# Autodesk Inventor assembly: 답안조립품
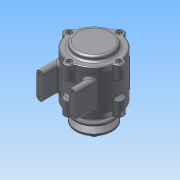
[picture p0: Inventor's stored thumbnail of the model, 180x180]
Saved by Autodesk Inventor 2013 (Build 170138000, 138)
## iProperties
Created: 2015-03
Part Number: 답안조립품
Document SubType Name: Assembly
Designer: ST5
Author: ST5
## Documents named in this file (11)
- C:\Users\ST5\Desktop\450305V1010\답안조립품.iam
- C:\Users\ST5\Desktop\450305V1010\1-본체.ipt
- C:\Users\ST5\Desktop\450305V1010\커버2.ipt
- C:\Users\ST5\Desktop\450305V1010\커버.ipt
- C:\Users\ST5\Desktop\450305V1010\베어링 6204.ipt
- C:\Users\ST5\Desktop\450305V1010\축.ipt
- C:\Users\ST5\Desktop\450305V1010\키(4 x 4 x 12).ipt
- C:\Users\ST5\Desktop\450305V1010\V벨트풀리.ipt
- C:\Users\ST5\Desktop\450305V1010\오일실.ipt
- C:\Users\ST5\Desktop\450305V1010\너트 M12x1.25.ipt
- C:\Users\ST5\Desktop\450305V1010\M 4 x 12.ipt
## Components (15 placed, 7 different names)
1. 1-본체:1
2. KS B 2023 6204 - 20 x 47 x 14:1
3. KS B 2023 6204 - 20 x 47 x 14:2
4. KS B 1311 (I) 4 x 4 x 12:1 — 각도:1
5. 그루브 풀리1:1
6. KS B 2804 D D - 20 32 8:1
7. KS B 1012 클래스 1 일반 - 미터 M12x1.25:1
8. KS B 1003 - 미터 M 4 x 12:1
9. KS B 1003 - 미터 M 4 x 12:2
10. KS B 1003 - 미터 M 4 x 12:3
11. KS B 1003 - 미터 M 4 x 12:4
12. KS B 1003 - 미터 M 4 x 12:5
13. KS B 1003 - 미터 M 4 x 12:6
14. KS B 1003 - 미터 M 4 x 12:7
15. KS B 1003 - 미터 M 4 x 12:8
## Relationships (1: Angle 1)
- 각도:1 [Angle]: KS B 1311 (I) 4 x 4 x 12:1
